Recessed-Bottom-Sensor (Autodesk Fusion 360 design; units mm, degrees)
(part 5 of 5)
sketch "Local raised mounting-tab clearance" plane through (-36.5, 0, 0) normal (1, 0, 0) x axis (0, 0, -1)
  line L1 (-54.9, -61.5) -> (-54.9, -96)
  line L2 (-58.1, -61.5) -> (-54.9, -61.5)
  line L3 (-58.1, -96) -> (-58.1, -61.5)
  line L4 (-54.9, -96) -> (-58.1, -96)
extrude "Extrude3" cut sketch "Local raised mounting-tab clearance" along normal blind 13
work_plane "WorkPlane4" AlongDistance -36.5 ExtraOffset 0
sketch "Local raised mounting-tab clearance (1)" plane through (-36.5, 0, 0) normal (1, 0, 0) x axis (0, 0, -1)
  line L1 (-54.9, 96) -> (-54.9, 61.5)
  line L2 (-58.1, 96) -> (-54.9, 96)
  line L3 (-58.1, 61.5) -> (-58.1, 96)
  line L4 (-54.9, 61.5) -> (-58.1, 61.5)
extrude "Extrude4" cut sketch "Local raised mounting-tab clearance (1)" along normal blind 13
work_plane "WorkPlane5" AlongDistance 23.5 ExtraOffset 0
sketch "Local raised mounting-tab clearance (2)" plane through (23.5, 0, 0) normal (1, 0, 0) x axis (0, 0, -1)
  line L1 (-54.9, -61.5) -> (-54.9, -96)
  line L2 (-58.1, -61.5) -> (-54.9, -61.5)
  line L3 (-58.1, -96) -> (-58.1, -61.5)
  line L4 (-54.9, -96) -> (-58.1, -96)
extrude "Extrude5" cut sketch "Local raised mounting-tab clearance (2)" along normal blind 13
work_plane "WorkPlane6" AlongDistance 23.5 ExtraOffset 0
sketch "Local raised mounting-tab clearance (3)" plane through (23.5, 0, 0) normal (1, 0, 0) x axis (0, 0, -1)
  line L1 (-54.9, 96) -> (-54.9, 61.5)
  line L2 (-58.1, 96) -> (-54.9, 96)
  line L3 (-58.1, 61.5) -> (-58.1, 96)
  line L4 (-54.9, 61.5) -> (-58.1, 61.5)
extrude "Extrude6" cut sketch "Local raised mounting-tab clearance (3)" along normal blind 13
ground "Pin154"
work_plane "WorkPlane78" AlongDistance -36.1 ExtraOffset 0
sketch "Preserve crossblock screw through suspension arm" plane through (-36.1, 0, 0) normal (1, 0, 0) x axis (0, 0, -1)
  circle C1 centre (-53.5, -62) radius 1.7
extrude "Extrude78" cut sketch "Preserve crossblock screw through suspension arm" along normal blind 12.2
work_plane "WorkPlane79" AlongDistance -36.1 ExtraOffset 0
sketch "Preserve crossblock screw through suspension arm (1)" plane through (-36.1, 0, 0) normal (1, 0, 0) x axis (0, 0, -1)
  circle C1 centre (-53.5, -70) radius 1.7
extrude "Extrude79" cut sketch "Preserve crossblock screw through suspension arm (1)" along normal blind 12.2
work_plane "WorkPlane98" AlongDistance 23.9 ExtraOffset 0
sketch "Preserve crossblock screw through suspension arm" plane through (23.9, 0, 0) normal (1, 0, 0) x axis (0, 0, -1)
  circle C1 centre (-53.5, -62) radius 1.7
extrude "Extrude98" cut sketch "Preserve crossblock screw through suspension arm" along normal blind 12.2
work_plane "WorkPlane99" AlongDistance 23.9 ExtraOffset 0
sketch "Preserve crossblock screw through suspension arm (1)" plane through (23.9, 0, 0) normal (1, 0, 0) x axis (0, 0, -1)
  circle C1 centre (-53.5, -70) radius 1.7
extrude "Extrude99" cut sketch "Preserve crossblock screw through suspension arm (1)" along normal blind 12.2
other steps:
create_component "CreateComponent1"
create_component "CreateComponent2"
create_component "CreateComponent3"
create_component "CreateComponent4"
create_component "CreateComponent5"
create_component "CreateComponent7"
create_component "CreateComponent8"
create_component "CreateComponent9"
create_component "CreateComponent10"
create_component "CreateComponent11"
create_component "CreateComponent12"
create_component "CreateComponent13"
create_component "CreateComponent14"
create_component "CreateComponent16"
create_component "CreateComponent28"
create_component "CreateComponent29"
create_component "CreateComponent49"
create_component "CreateComponent89"
create_component "CreateComponent90"
create_component "CreateComponent144"
create_component "CreateComponent145"
create_component "CreateComponent146"
create_component "CreateComponent147"
create_component "CreateComponent148"
create_component "CreateComponent149"
create_component "CreateComponent150"
create_component "CreateComponent151"
create_component "CreateComponent152"
create_component "CreateComponent153"
create_component "CreateComponent154"
create_component "CreateComponent155"
create_component "CreateComponent156"
create_component "CreateComponent157"
create_component "CreateComponent158"
create_component "CreateComponent159"
create_component "CreateComponent160"
create_component "CreateComponent161"
create_component "CreateComponent171"
create_component "CreateComponent172"
create_component "CreateComponent173"
create_component "CreateComponent174"
create_component "CreateComponent175"
create_component "CreateComponent176"
create_component "CreateComponent177"
create_component "CreateComponent178"
create_component "CreateComponent179"
create_component "CreateComponent180"
create_component "CreateComponent181"
create_component "CreateComponent182"
create_component "CreateComponent183"
create_component "CreateComponent184"
create_component "CreateComponent185"
create_component "CreateComponent186"
create_component "CreateComponent188"
create_component "CreateComponent193"
create_component "CreateComponent194"
create_component "CreateComponent195"
create_component "CreateComponent196"
create_component "CreateComponent201"
create_component "CreateComponent202"
create_component "CreateComponent203"
create_component "CreateComponent204"
create_component "CreateComponent206"
create_component "CreateComponent207"
create_component "CreateComponent208"
create_component "CreateComponent209"
create_component "CreateComponent210"
named bodies: "P01R Top-rail hanging left sideplate", "P02R Top-rail hanging right sensor sideplate", "P03 Left flanged journal bush", "P04 Right flanged journal bush", "P06 Shaft retaining cap", "P07 Integral lever rotor and cam carrier", "P08 Cam 7 gates - stable endpoints", "P08 Cam 5 gates - stable endpoints", "P08 Cam 3 gates - stable endpoints", "P09 Grip insert half", "P10 Grip screw half", "P11 Forked roller follower", "P13 Spring reaction crossblock", "P21 Follower left axial spacer", "P22 Follower right axial spacer", "HARDWARE Roller axle M3 nut", "P23 Left rotor thrust spacer", "P24 Right rotor thrust spacer", "P25 Captured printed pivot lower half", "P26 Captured printed pivot upper half", "HARDWARE Grip M3x20 cap head 180", "HARDWARE Grip M3x20 cap head 190", "HARDWARE Stop M3x20 cap head -1", "HARDWARE Stop M3 plain captive nut -1", "HARDWARE Stop M3x20 cap head 1", "HARDWARE Stop M3 plain captive nut 1", "HARDWARE 623ZZ roller bearing at 8", "HARDWARE 623ZZ roller bearing at 12", "P27 Printed guide sleeve 4", "HARDWARE Cup guide M3x12 4", "P27 Printed guide sleeve 20", "HARDWARE Cup guide M3x12 20", "P14 Captive spring cup for 9 mm spring", "P15 Recessed preload limit collar 1 mm", "HARDWARE Preload M3x20 cap head", "REFERENCE Stock spring OD9 wire1 free20 - rate and solid height assumed", "HARDWARE Shaft joining M3x8 -15", "HARDWARE Shaft joining M3x8 15", "P28 Shaft alignment key -5", "P28 Shaft alignment key 5", "HARDWARE Main shaft cap M3x8 cap head", "HARDWARE Cam M3x10 cap head -45", "HARDWARE Cam M3x10 cap head 0", "HARDWARE Cam M3x10 cap head 45", "HARDWARE Roller axle M3x20 cap head", "HARDWARE Crossblock M3x20 cap head (-62, -1)", "HARDWARE Crossblock M3x20 cap head (-62, 1)", "HARDWARE Crossblock M3x20 cap head (-70, -1)", "HARDWARE Crossblock M3x20 cap head (-70, 1)", "HARDWARE Rotor clamp M3x16 cap head", "P05G Shaft lower half", "P05G Shaft upper half", "G01R 48T gear with upper clamp", "G02 24T sensor pinion", "REFERENCE Geared RK097 provisional envelope", "HARDWARE Geared RK097 supplied washer ASSUMED", "HARDWARE Geared RK097 supplied nut ASSUMED", "HARDWARE G02 24T sensor pinion clamp M3x12", "HARDWARE G01 upper clamp M3x12", "G03R Lower removable potentiometer panel"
